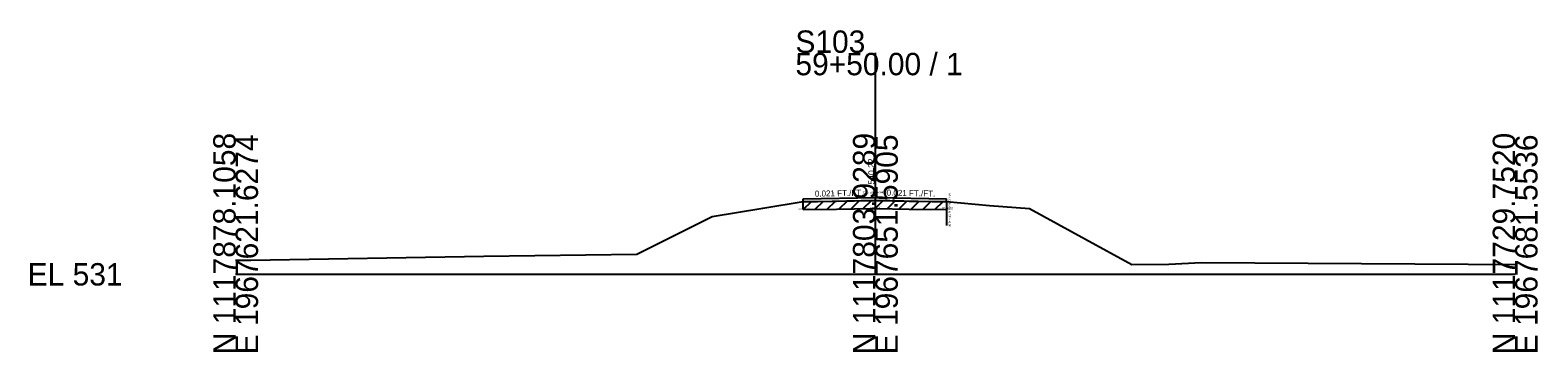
# Model space of a CAD drawing. Extents: x -26 to 163, y -10 to 24018.
# Drawn here: x -25.7 to 162.8, y 8990.3 to 9030.5 of the extents above; entities that cross this region are included whole.
import ezdxf

# ---------------------------------------------------------------- set-up
doc = ezdxf.new("R2010")
doc.units = 0
for name, color, linetype in [('RD_GPK_XS_Cell', 7, 'Continuous'), ('RD_XS_ExGround', 7, 'Continuous'), ('RD_XS_ExPaveRet', 7, 'Continuous'), ('RD_XS_Misc_Line', 7, 'Continuous'), ('RD_XS_PaveOvlay_CP', 7, 'Continuous'), ('RD_XS_TX_Elev_EX', 7, 'Continuous'), ('RD_XS_TX_ExEOP', 7, 'Continuous'), ('RD_XS_TX_Notes', 7, 'Continuous'), ('RD_XS_TX_Profile', 7, 'Continuous'), ('RD_XS_TX_Slope', 7, 'Continuous')]:
    doc.layers.add(name, color=color, linetype=linetype)

msp = doc.modelspace()

# ---------------------------------------------------------------- linework, layer by layer
at = {"layer": 'RD_GPK_XS_Cell'}
for p, q in [((80, 9000), (80, 9027.69)), ((0, 9000), (80, 9000)), ((80, 9000), (160, 9000))]:
    msp.add_line(p, q, dxfattribs=at)
at = {"layer": 'RD_XS_ExGround'}
msp.add_lwpolyline([(0, 9001.79), (1.89, 9001.78), (31.04, 9002.26), (50.17, 9002.52), (55.1, 9004.99), (59.59, 9007.22), (65.94, 9008.28), (70.99, 9009.1), (75.13, 9009.16), (79.57, 9009.23), (80, 9009.22), (84.24, 9009.16), (88.91, 9009.12), (94.28, 9008.62), (99.29, 9008.21), (106.27, 9004.38), (112.07, 9001.21), (116.71, 9001.29), (120.77, 9001.49), (154.11, 9001.29), (160, 9001.22)], dxfattribs=at)
at = {"layer": 'RD_XS_ExPaveRet'}
for p, q in [((70.99, 9008.1), (72, 9009.12)), ((70.99, 9008.1), (70.99, 9009.1)), ((70.99, 9008.1), (75.13, 9008.16)), ((72.49, 9008.13), (73.5, 9009.14)), ((73.99, 9008.15), (75, 9009.16)), ((75.13, 9008.16), (79.57, 9008.23)), ((75.49, 9008.17), (76.5, 9009.18)), ((76.99, 9008.19), (78, 9009.21)), ((78.49, 9008.21), (79.5, 9009.23)), ((79.57, 9008.23), (80, 9008.22)), ((79.99, 9008.22), (80.97, 9009.21)), ((80, 9008.22), (84.24, 9008.16)), ((81.49, 9008.2), (82.47, 9009.19)), ((82.99, 9008.18), (83.97, 9009.17)), ((84.24, 9008.16), (88.91, 9008.12)), ((84.49, 9008.16), (85.48, 9009.15)), ((85.99, 9008.15), (86.98, 9009.14)), ((87.49, 9008.13), (88.48, 9009.12)), ((88.91, 9009.12), (88.91, 9008.12))]:
    msp.add_line(p, q, dxfattribs=at)
at = {"layer": 'RD_XS_Misc_Line'}
msp.add_line((88.91, 9009.12), (88.91, 9006.12), dxfattribs=at)
at = {"layer": 'RD_XS_PaveOvlay_CP'}
for p, q in [((70.99, 9009.43), (80, 9009.62)), ((70.99, 9009.1), (70.99, 9009.43)), ((80, 9009.22), (70.99, 9009.04)), ((80, 9009.62), (88.91, 9009.44)), ((88.91, 9009.04), (80, 9009.22)), ((88.91, 9009.12), (88.91, 9009.44))]:
    msp.add_line(p, q, dxfattribs=at)

# ---------------------------------------------------------------- texts
at = {"layer": 'RD_GPK_XS_Cell'}
for s, p in [('S103', (70, 9027.69)), ('59+50.00 / 1', (70, 9024.89)), ('EL 531', (-26, 8998.6))]:
    msp.add_text(s, height=2.8, dxfattribs=at).set_placement(p)
for s, p in [('N 1117878.1058', (0, 8990)), ('N 1117729.7520', (160, 8990)), ('E 1967621.6274', (2.8, 8990)), ('N 1117803.9289', (80, 8990)), ('E 1967651.5905', (82.8, 8990)), ('E 1967681.5536', (162.8, 8990))]:
    msp.add_text(s, height=2.8, rotation=90, dxfattribs=at).set_placement(p)
at = {"layer": 'RD_XS_TX_Elev_EX'}
msp.add_text('540.22', height=0.8, rotation=90, dxfattribs=at).set_placement((79.9, 9011.22))
at = {"layer": 'RD_XS_TX_ExEOP'}
for s, p in [('EOP-L', (70.94, 9009.43)), ('EOP-R', (88.86, 9009.44))]:
    msp.add_text(s, height=0.1, rotation=270, dxfattribs=at).set_placement(p)
at = {"layer": 'RD_XS_TX_Notes'}
for s, p in [('Elev. @CL = 540.62', (78.47, 9010.12)), (' dE= 0.33', (70.28, 9008.1)), (' dE= 0.40', (79.29, 9008.22)), (' dE= 0.32', (88.2, 9008.12))]:
    msp.add_text(s, height=0.25, dxfattribs=at).set_placement(p)
msp.add_text(' Min. Distance @CP = -0.08', height=0.25, rotation=270, dxfattribs=at).set_placement((89.16, 9010.21))
at = {"layer": 'RD_XS_TX_Profile'}
msp.add_text('CL', height=0.25, dxfattribs=at).set_placement((79.77, 9009.62))
at = {"layer": 'RD_XS_TX_Slope'}
for rotation, p in [(1.1916, (72.44, 9009.71)), (358.8084, (81.41, 9009.84))]:
    msp.add_text('0.021 FT./FT.', height=0.75, rotation=rotation, dxfattribs=at).set_placement(p)

doc.saveas('drawing.dxf')
